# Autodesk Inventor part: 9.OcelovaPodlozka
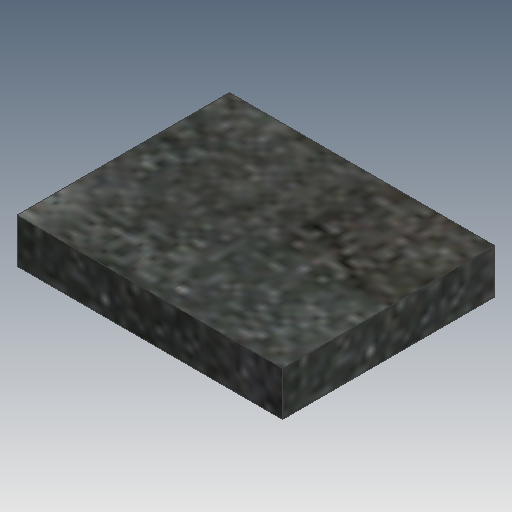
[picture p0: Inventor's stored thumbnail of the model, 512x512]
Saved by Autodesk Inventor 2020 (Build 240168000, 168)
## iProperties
Created: 2022-02
Part Number: 9.OcelovaPodlozka
Material: Steel
Document SubType Name: Modeling
Designer: marti
Density: 7.85 g/cm^3
Appearance: Plate
Mass: 28.26 g
Surface Area: 19.8 cm^2
Volume: 3.6 cm^3
Author: marti
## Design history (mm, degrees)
sketch "Sketch1"
  geometry: L1 (15, 12)-(-15, 12); L2 (-15, 12)-(-15, -12); L3 (-15, -12)-(15, -12); L4 (15, -12)-(15, 12); L5 (15, 12)-(-15, -12); L6 (-15, 12)-(15, -12); 1 further point
  constraints: 12 end point, 2 midpoint, 2 parallel, 1 horizontal, 1 perpendicular
  dimensions: "d0" = 30 distance of L3.end L2.end; "d1" = 24 distance of L2.end L1.end
extrude "Extrusion1" new body sketch "Sketch1" distance "d2" = 5; taper "d3" = 0 deg
body "Solid1"
